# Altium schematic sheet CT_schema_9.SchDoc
size 405 x 220 mm
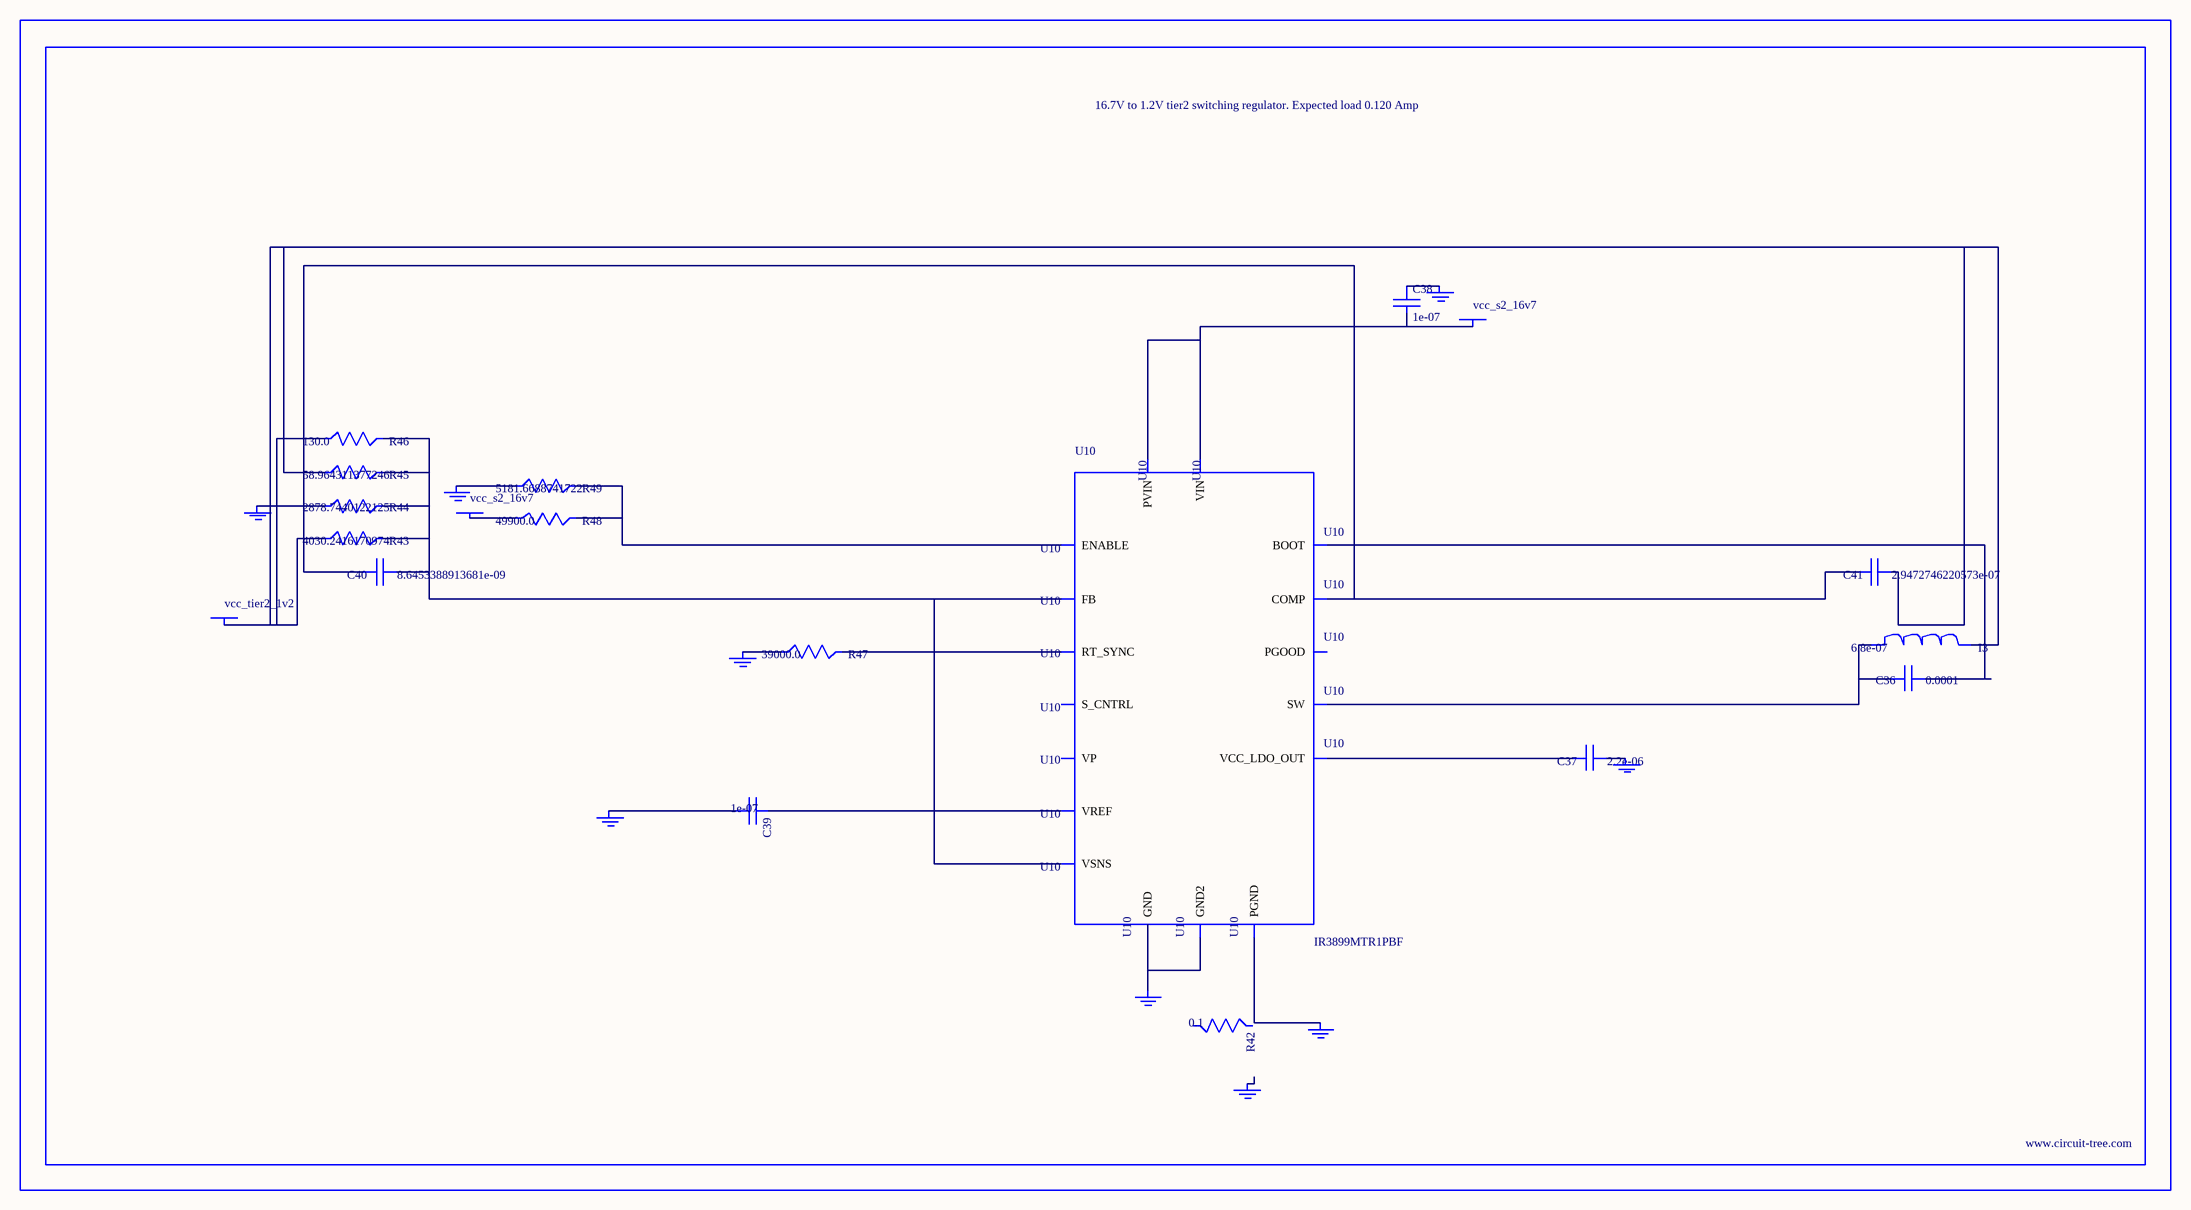
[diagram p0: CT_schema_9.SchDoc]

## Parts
BORDER8  (no value)
C36  0.0001  [C1210]
C37  2.2e-06  [C0603]
C38  1e-07  [C0402]
C39  1e-07  [C0402]
C40  8.6453388913681e-09  [R0603]
C41  2.9472746220573e-07  [R0603]
GND_INSTANCE_8_0  (no value)
GND_INSTANCE_8_1  (no value)
GND_INSTANCE_8_2  (no value)
GND_INSTANCE_8_3  (no value)
GND_INSTANCE_8_4  (no value)
GND_INSTANCE_8_5  (no value)
GND_INSTANCE_8_6  (no value)
GND_INSTANCE_8_7  (no value)
GND_INSTANCE_8_8  (no value)
I3  6.8e-07  [IND25X25CZ]
POWER_INSTANCE_8_0  vcc_s2_16v7
POWER_INSTANCE_8_1  vcc_s2_16v7
POWER_INSTANCE_8_2  vcc_tier2_1v2
R42  0.1  [R0603]
R43  4030.2416170974  [R0603]
R44  2878.7440122125  [R0603]
R45  58.964311377246  [R0603]
R46  130.0  [R0603]
R47  39000.0  [R0603]
R48  49900.0  [R0603]
R49  5181.6688741722  [R0603]
U10  IR3899MTR1PBF  [IR3899MTR1PBF]

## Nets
NetC36_1: C36.1 U10.14(BOOT)
NetC36_2: C36.2 I3.1 U10.12(SW)
NetC37_1: C37.1 GND_INSTANCE_8_4.0(GND)
NetC37_2: C37.2 U10.10(VCC_LDO_OUT)
NetC38_1: C38.1 GND_INSTANCE_8_3.0(GND)
NetC38_2: C38.2 POWER_INSTANCE_8_0.0(PWR) U10.9(VIN) U10.13(PVIN)
NetC39_1: C39.1 U10.2(VREF)
NetC39_2: C39.2 GND_INSTANCE_8_1.0(GND)
NetC40_1: C40.1 R43.2 R44.2 R45.2 R46.2 U10.1(FB) U10.8(VSNS)
NetC40_2: C40.2 C41.2 U10.3(COMP)
NetC41_1: C41.1 I3.2 POWER_INSTANCE_8_2.0(PWR) R43.1 R45.1 R46.1
NetGND_INSTANCE_8_0_0: GND_INSTANCE_8_0.0(GND) R44.1
NetGND_INSTANCE_8_2_0: GND_INSTANCE_8_2.0(GND) R47.1
NetGND_INSTANCE_8_6_0: GND_INSTANCE_8_6.0(GND) U10.11(PGND)
NetGND_INSTANCE_8_7_0: GND_INSTANCE_8_7.0(GND) R49.1
NetGND_INSTANCE_8_8_0: GND_INSTANCE_8_8.0(GND) U10.4(GND) U10.17(GND2)
NetPOWER_INSTANCE_8_1_0: POWER_INSTANCE_8_1.0(PWR) R48.1
NetR47_2: R47.2 U10.5(RT_SYNC)
NetR48_2: R48.2 R49.2 U10.15(ENABLE)

Not connected (* = marked no-connect by the designer): GND_INSTANCE_8_5 0(GND); R42 1 2; U10 6(S_CNTRL) 7(PGOOD) 16(VP)

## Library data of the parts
BORDER8 = BORDER_PAGE8
C36 = GRM32ER61A107ME20L
C37 = C0603C225K8RACTU
C38 C39 = C0402C104K3RACTU
C40 = C40
C41 = C41
GND_INSTANCE_8_0-GND_INSTANCE_8_8 = GND
I3 = IHLP2525CZERR68M01
POWER_INSTANCE_8_0-POWER_INSTANCE_8_2 = PWR
R42 = ERJ-3RSFR10V
R43 = R43
R44 = R44
R45 = R45
R46 = RC0603JR-07130RL
R47 = RC0603JR-0739KL
R48 = RC0603FR-0749K9
R49 = R49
